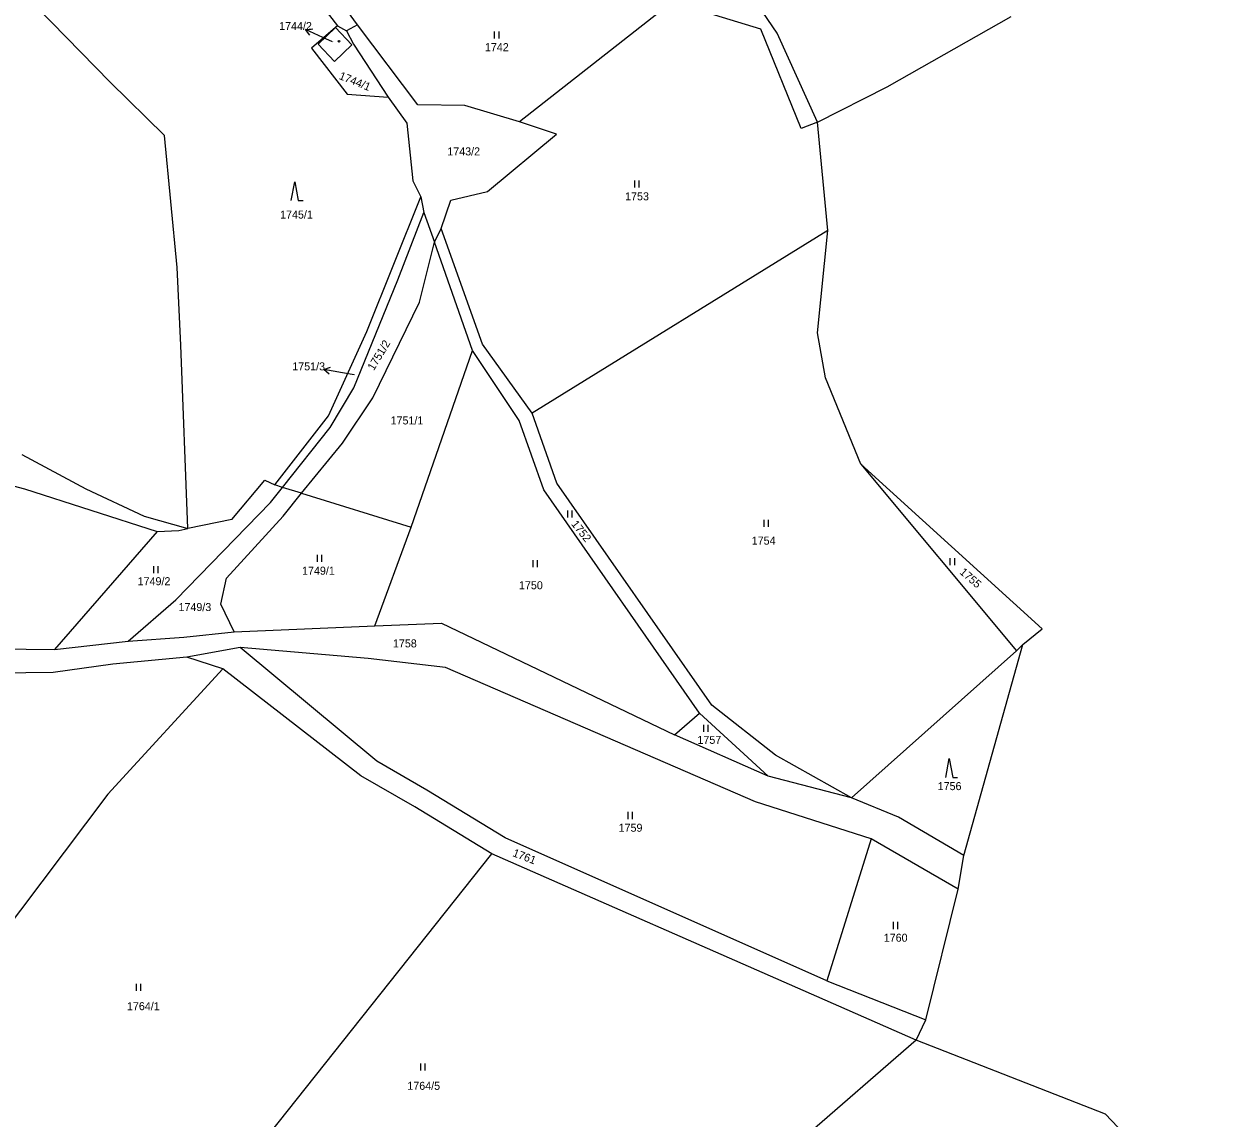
# Model space of a CAD drawing. Extents: x -670359 to -668019, y -978807 to -976674.
# Drawn here: x -668901.1 to -668648.7, y -978283.1 to -978050.6 of the extents above; entities that cross this region are included whole.
import ezdxf

# ---------------------------------------------------------------- set-up
doc = ezdxf.new("R2010")
doc.units = 0
for name, color, linetype in [('Hranice kat_území', 7, 'Continuous'), ('Hranice parcel', 7, 'Continuous'), ('Parcelní čísla', 7, 'Continuous'), ('Značky budov', 7, 'Continuous'), ('Značky kultur', 7, 'Continuous')]:
    doc.layers.add(name, color=color, linetype=linetype)

msp = doc.modelspace()

# ---------------------------------------------------------------- linework, layer by layer
at = {"layer": 'Hranice kat_území'}
for points in [[(-668717.71, -978064.03), (-668691.36, -978049.13)], [(-668732.49, -978071.53), (-668717.71, -978064.03)], [(-668730.32, -978094.52), (-668732.49, -978071.53)], [(-668732.46, -978116.32), (-668730.32, -978094.52)], [(-668730.79, -978125.87), (-668732.46, -978116.32)], [(-668723.26, -978144.16), (-668730.79, -978125.87)], [(-668684.8, -978179.16), (-668723.26, -978144.16)], [(-668688.86, -978182.53), (-668684.8, -978179.16)], [(-668701.4, -978227.34), (-668688.86, -978182.53)], [(-668702.65, -978234.44), (-668701.4, -978227.34)], [(-668709.45, -978262.24), (-668702.65, -978234.44)], [(-668711.53, -978266.52), (-668709.45, -978262.24)], [(-668671.3, -978282.27), (-668711.53, -978266.52)], [(-668648.66, -978306.11), (-668671.3, -978282.27)]]:
    msp.add_lwpolyline(points, dxfattribs=at)
at = {"layer": 'Hranice parcel'}
for points in [[(-668850.01, -978030.9), (-668834.43, -978051.09)], [(-668830.18, -978050.85), (-668836.59, -978042.09)], [(-668741.05, -978052.66), (-668747.13, -978043.67)], [(-668763.34, -978046.02), (-668795.8, -978071.45)], [(-668744.55, -978051.8), (-668763.34, -978046.02)], [(-668882.71, -978063.01), (-668898.28, -978047.1)], [(-668834.85, -978051.44), (-668839.95, -978055.79)], [(-668831.37, -978055.1), (-668835.04, -978058.62), (-668838.54, -978054.94), (-668834.85, -978051.44)], [(-668834.43, -978051.09), (-668834.85, -978051.44)], [(-668834.85, -978051.44), (-668831.37, -978055.1)], [(-668834.43, -978051.09), (-668832.52, -978052.16)], [(-668830.18, -978050.85), (-668832.52, -978052.16)], [(-668817.35, -978067.87), (-668830.18, -978050.85)], [(-668832.52, -978052.16), (-668831.05, -978054.99)], [(-668735.95, -978072.91), (-668744.55, -978051.8)], [(-668732.49, -978071.53), (-668741.05, -978052.66)], [(-668839.95, -978055.79), (-668832.36, -978065.61)], [(-668831.05, -978054.99), (-668823.64, -978066.24)], [(-668871.19, -978074.38), (-668882.71, -978063.01)], [(-668832.36, -978065.61), (-668823.64, -978066.24)], [(-668823.64, -978066.24), (-668819.74, -978071.75)], [(-668807.4, -978068.01), (-668817.35, -978067.87)], [(-668795.8, -978071.45), (-668807.4, -978068.01)], [(-668819.74, -978071.75), (-668818.43, -978084.01)], [(-668787.9, -978074.1), (-668795.8, -978071.45)], [(-668732.49, -978071.53), (-668735.95, -978072.91)], [(-668868.49, -978102.38), (-668871.19, -978074.38)], [(-668802.6, -978086.3), (-668787.9, -978074.1)], [(-668818.43, -978084.01), (-668816.73, -978087.4)], [(-668810.4, -978088.1), (-668802.6, -978086.3)], [(-668828.18, -978116), (-668816.73, -978087.4)], [(-668816.73, -978087.4), (-668816.1, -978090.7)], [(-668812.45, -978094.15), (-668810.4, -978088.1)], [(-668821.6, -978105.05), (-668816.1, -978090.7)], [(-668816.1, -978090.7), (-668813.8, -978097)], [(-668813.8, -978097), (-668812.45, -978094.15)], [(-668803.66, -978118.67), (-668812.45, -978094.15)], [(-668730.32, -978094.52), (-668793.11, -978133.33)], [(-668817.05, -978109.8), (-668813.8, -978097)], [(-668805.76, -978120.07), (-668813.8, -978097)], [(-668867.7, -978118.91), (-668868.49, -978102.38)], [(-668831, -978128), (-668821.6, -978105.05)], [(-668826.9, -978130.1), (-668817.05, -978109.8)], [(-668836.34, -978133.93), (-668828.18, -978116)], [(-668866.22, -978157.86), (-668867.7, -978118.91)], [(-668793.11, -978133.33), (-668803.66, -978118.67)], [(-668818.82, -978157.6), (-668805.76, -978120.07)], [(-668795.86, -978134.88), (-668805.76, -978120.07)], [(-668836, -978136.4), (-668831, -978128)], [(-668833.4, -978139.7), (-668826.9, -978130.1)], [(-668847.72, -978148.61), (-668836.34, -978133.93)], [(-668790.59, -978149.62), (-668795.86, -978134.88)], [(-668787.84, -978148.22), (-668793.11, -978133.33)], [(-668846.11, -978149.11), (-668836, -978136.4)], [(-668842.07, -978150.37), (-668833.4, -978139.7)], [(-668901.51, -978142.11), (-668887.86, -978149.46)], [(-668926.62, -978142.66), (-668900.88, -978149.43)], [(-668723.26, -978144.16), (-668690.25, -978183.86)], [(-668856.89, -978155.97), (-668849.86, -978147.61)], [(-668849.86, -978147.61), (-668847.72, -978148.61)], [(-668900.88, -978149.43), (-668872.7, -978158.49)], [(-668887.86, -978149.46), (-668875.51, -978155.2)], [(-668848.65, -978152.3), (-668846.11, -978149.11)], [(-668846.11, -978149.11), (-668847.72, -978148.61)], [(-668842.07, -978150.37), (-668846.11, -978149.11)], [(-668757.55, -978197.08), (-668790.59, -978149.62)], [(-668754.96, -978195.36), (-668787.84, -978148.22)], [(-668868.8, -978173), (-668848.65, -978152.3)], [(-668846, -978155.2), (-668842.07, -978150.37)], [(-668842.07, -978150.37), (-668818.82, -978157.6)], [(-668875.51, -978155.2), (-668866.22, -978157.86)], [(-668856.89, -978155.97), (-668866.22, -978157.86)], [(-668858, -978168.4), (-668846, -978155.2)], [(-668826.54, -978178.5), (-668818.82, -978157.6)], [(-668872.7, -978158.49), (-668894.51, -978183.54)], [(-668872.7, -978158.49), (-668868.14, -978158.25)], [(-668868.14, -978158.25), (-668866.22, -978157.86)], [(-668859.2, -978173.9), (-668858, -978168.4)], [(-668878.9, -978181.8), (-668868.8, -978173)], [(-668856.4, -978179.8), (-668859.2, -978173.9)], [(-668867.09, -978180.91), (-668856.4, -978179.8)], [(-668856.4, -978179.8), (-668826.54, -978178.5)], [(-668826.54, -978178.5), (-668812.37, -978177.95)], [(-668812.37, -978177.95), (-668762.83, -978201.7)], [(-668894.51, -978183.54), (-668878.9, -978181.8)], [(-668878.9, -978181.8), (-668867.09, -978180.91)], [(-668688.86, -978182.53), (-668690.25, -978183.86)], [(-668906.67, -978183.41), (-668894.51, -978183.54)], [(-668866.44, -978185.16), (-668882.15, -978186.64)], [(-668855.12, -978183.12), (-668866.44, -978185.16)], [(-668858.8, -978187.69), (-668866.44, -978185.16)], [(-668827.94, -978185.44), (-668855.12, -978183.12)], [(-668826.08, -978207.31), (-668855.12, -978183.12)], [(-668811.49, -978187.41), (-668827.94, -978185.44)], [(-668690.25, -978183.86), (-668725.29, -978215.08)], [(-668882.15, -978186.64), (-668894.83, -978188.42)], [(-668858.8, -978187.69), (-668883.19, -978214.3)], [(-668829.5, -978210.37), (-668858.8, -978187.69)], [(-668745.63, -978215.92), (-668811.49, -978187.41)], [(-668894.83, -978188.42), (-668918.21, -978188.72)], [(-668741.38, -978206), (-668754.96, -978195.36)], [(-668762.83, -978201.7), (-668757.55, -978197.08)], [(-668742.97, -978210.45), (-668757.55, -978197.08)], [(-668742.97, -978210.45), (-668762.83, -978201.7)], [(-668815.46, -978213.41), (-668826.08, -978207.31)], [(-668725.29, -978215.08), (-668741.38, -978206)], [(-668818, -978216.97), (-668829.5, -978210.37)], [(-668725.29, -978215.08), (-668742.97, -978210.45)], [(-668883.19, -978214.3), (-668915.88, -978257.56)], [(-668798.83, -978223.55), (-668815.46, -978213.41)], [(-668715.27, -978219.18), (-668725.29, -978215.08)], [(-668801.69, -978226.94), (-668818, -978216.97)], [(-668721.11, -978223.8), (-668745.63, -978215.92)], [(-668701.4, -978227.34), (-668715.27, -978219.18)], [(-668730.52, -978253.95), (-668798.83, -978223.55)], [(-668721.11, -978223.8), (-668730.52, -978253.95)], [(-668702.65, -978234.44), (-668721.11, -978223.8)], [(-668886.37, -978333.7), (-668801.69, -978226.94)], [(-668732.66, -978257.27), (-668801.69, -978226.94)], [(-668730.52, -978253.95), (-668709.45, -978262.24)], [(-668711.53, -978266.52), (-668732.66, -978257.27)], [(-668711.53, -978266.52), (-668735.82, -978287.61)]]:
    msp.add_lwpolyline(points, dxfattribs=at)
at = {"layer": 'Parcelní čísla'}
for p, q in [((-668840.33, -978053.09), (-668841.2, -978051.87)), ((-668835.48, -978054.48), (-668837.56, -978053.53)), ((-668836.17, -978125.05), (-668837.32, -978124.08)), ((-668830.92, -978125.23), (-668833.38, -978124.79))]:
    msp.add_line(p, q, dxfattribs=at)
for points in [[(-668837.56, -978053.53), (-668841.2, -978051.87), (-668839.7, -978051.73)], [(-668833.38, -978124.79), (-668837.32, -978124.08), (-668835.91, -978123.58)]]:
    msp.add_lwpolyline(points, dxfattribs=at)
at = {"layer": 'Značky budov'}
msp.add_circle((-668834.11, -978054.35), 0.175, dxfattribs=at)
at = {"layer": 'Značky kultur'}
for p, q in [((-668801.13, -978052.26), (-668801.13, -978053.76)), ((-668800.13, -978053.76), (-668800.13, -978052.26)), ((-668771.35, -978083.94), (-668771.35, -978085.44)), ((-668770.35, -978085.44), (-668770.35, -978083.94)), ((-668785.58, -978154.02), (-668785.58, -978155.52)), ((-668784.58, -978155.52), (-668784.58, -978154.02)), ((-668743.87, -978155.99), (-668743.87, -978157.49)), ((-668742.87, -978157.49), (-668742.87, -978155.99)), ((-668838.78, -978163.47), (-668838.78, -978164.97)), ((-668837.78, -978164.97), (-668837.78, -978163.47)), ((-668792.98, -978164.56), (-668792.98, -978166.06)), ((-668791.98, -978166.06), (-668791.98, -978164.56)), ((-668704.36, -978164.13), (-668704.36, -978165.63)), ((-668703.36, -978165.63), (-668703.36, -978164.13)), ((-668873.51, -978165.82), (-668873.51, -978167.32)), ((-668872.51, -978167.32), (-668872.51, -978165.82)), ((-668756.72, -978199.57), (-668756.72, -978201.07)), ((-668755.72, -978201.07), (-668755.72, -978199.57)), ((-668772.77, -978218.07), (-668772.77, -978219.57)), ((-668771.77, -978219.57), (-668771.77, -978218.07)), ((-668716.42, -978241.43), (-668716.42, -978242.93)), ((-668715.42, -978242.93), (-668715.42, -978241.43)), ((-668877.19, -978254.58), (-668877.19, -978256.08)), ((-668876.19, -978256.08), (-668876.19, -978254.58)), ((-668816.83, -978271.5), (-668816.83, -978273)), ((-668815.83, -978273), (-668815.83, -978271.5))]:
    msp.add_line(p, q, dxfattribs=at)
for points in [[(-668844.26, -978088.2), (-668843.51, -978084.2), (-668842.76, -978088.2), (-668841.76, -978088.2)], [(-668705.26, -978210.73), (-668704.51, -978206.73), (-668703.76, -978210.73), (-668702.76, -978210.73)]]:
    msp.add_lwpolyline(points, dxfattribs=at)
msp.add_circle((-668834.11, -978054.35), 0.175, dxfattribs=at)

# ---------------------------------------------------------------- texts
at = {"layer": 'Parcelní čísla'}
for s, height, p in [('1744/2', 1.7, (-668846.83, -978051.97)), ('1744/2', 0.1, (-668835.72, -978054.48)), ('1742', 1.7, (-668803.13, -978056.46)), ('1743/2', 1.7, (-668811.11, -978078.6)), ('1753', 1.7, (-668773.35, -978088.14)), ('1745/1', 1.7, (-668846.62, -978092.02)), ('1751/3', 1.7, (-668844.04, -978124.26)), ('1751/3', 0.1, (-668830.92, -978125.23)), ('1751/1', 1.7, (-668823.16, -978135.75)), ('1754', 1.7, (-668746.46, -978161.28)), ('1749/1', 1.7, (-668841.96, -978167.67)), ('1749/2', 1.7, (-668876.88, -978169.9)), ('1750', 1.7, (-668795.89, -978170.76)), ('1749/3', 1.7, (-668868.2, -978175.39)), ('1758', 1.7, (-668822.66, -978183.11)), ('1757', 1.7, (-668757.99, -978203.6)), ('1756', 1.7, (-668706.97, -978213.43)), ('1759', 1.7, (-668774.73, -978222.27)), ('1760', 1.7, (-668718.42, -978245.63)), ('1764/1', 1.7, (-668879.15, -978260.17)), ('1764/5', 1.7, (-668819.6, -978277.09))]:
    msp.add_text(s, height=height, dxfattribs=at).set_placement(p)
for s, rotation, p in [('1744/1', 337.9305, (-668834.26, -978062.33)), ('1751/2', 58.8972, (-668826.73, -978124.44)), ('1752', 308.5445, (-668784.88, -978156.95)), ('1755', 319.0495, (-668702.44, -978167.33)), ('1761', 338.9225, (-668797.38, -978227.41))]:
    msp.add_text(s, height=1.7, rotation=rotation, dxfattribs=at).set_placement(p)

doc.saveas('drawing.dxf')
